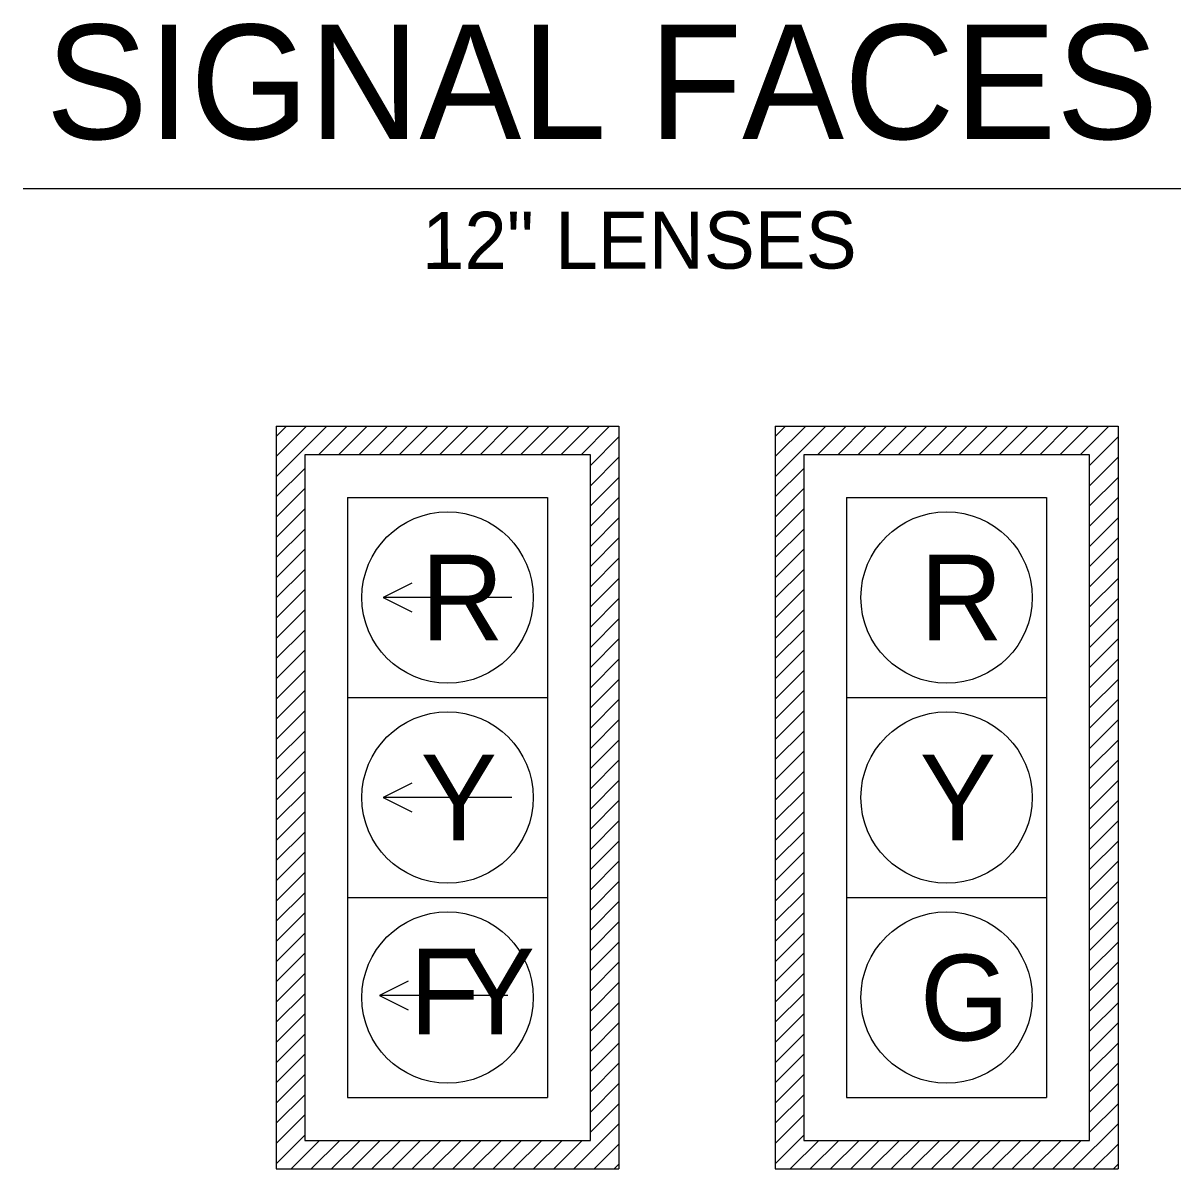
# Model space of a CAD drawing. Extents: x 1845362 to 1846362, y 750211 to 750851.
# Drawn here: x 1845538 to 1845618.5, y 750350.5 to 750430.7 of the extents above; entities that cross this region are included whole.
import ezdxf

# ---------------------------------------------------------------- set-up
doc = ezdxf.new("R2010")
doc.units = 0
doc.layers.add('T_Drafting', color=7, linetype='Continuous')
doc.layers.add('T_Notes', color=7, linetype='Continuous')

msp = doc.modelspace()

# ---------------------------------------------------------------- linework, layer by layer
at = {"layer": 'T_Drafting'}
for p, q in [((1845555.757, 750402.459), (1845579.757, 750402.459)), ((1845555.757, 750402.459), (1845555.757, 750350.459)), ((1845555.757, 750398.912), (1845559.304, 750402.459)), ((1845555.757, 750400.326), (1845557.89, 750402.459)), ((1845555.757, 750401.74), (1845556.475, 750402.459)), ((1845558.718, 750400.459), (1845560.718, 750402.459)), ((1845560.132, 750400.459), (1845562.132, 750402.459)), ((1845561.546, 750400.459), (1845563.546, 750402.459)), ((1845562.961, 750400.459), (1845564.961, 750402.459)), ((1845564.375, 750400.459), (1845566.375, 750402.459)), ((1845565.789, 750400.459), (1845567.789, 750402.459)), ((1845567.203, 750400.459), (1845569.203, 750402.459)), ((1845568.618, 750400.459), (1845570.618, 750402.459)), ((1845570.032, 750400.459), (1845572.032, 750402.459)), ((1845571.446, 750400.459), (1845573.446, 750402.459)), ((1845572.86, 750400.459), (1845574.86, 750402.459)), ((1845574.274, 750400.459), (1845576.274, 750402.459)), ((1845575.689, 750400.459), (1845577.689, 750402.459)), ((1845577.103, 750400.459), (1845579.103, 750402.459)), ((1845579.757, 750402.459), (1845579.757, 750350.459)), ((1845590.695, 750402.459), (1845614.695, 750402.459)), ((1845590.695, 750402.459), (1845590.695, 750350.459)), ((1845590.695, 750398.912), (1845594.242, 750402.459)), ((1845590.695, 750400.326), (1845592.827, 750402.459)), ((1845590.695, 750401.74), (1845591.413, 750402.459)), ((1845593.656, 750400.459), (1845595.656, 750402.459)), ((1845595.07, 750400.459), (1845597.07, 750402.459)), ((1845596.484, 750400.459), (1845598.484, 750402.459)), ((1845597.898, 750400.459), (1845599.898, 750402.459)), ((1845599.313, 750400.459), (1845601.313, 750402.459)), ((1845600.727, 750400.459), (1845602.727, 750402.459)), ((1845602.141, 750400.459), (1845604.141, 750402.459)), ((1845603.555, 750400.459), (1845605.555, 750402.459)), ((1845604.97, 750400.459), (1845606.97, 750402.459)), ((1845606.384, 750400.459), (1845608.384, 750402.459)), ((1845607.798, 750400.459), (1845609.798, 750402.459)), ((1845609.212, 750400.459), (1845611.212, 750402.459)), ((1845610.626, 750400.459), (1845612.626, 750402.459)), ((1845612.041, 750400.459), (1845614.041, 750402.459)), ((1845614.695, 750402.459), (1845614.695, 750350.459)), ((1845577.757, 750399.699), (1845579.757, 750401.699)), ((1845612.695, 750399.699), (1845614.695, 750401.699)), ((1845577.757, 750398.285), (1845579.757, 750400.285)), ((1845612.695, 750398.285), (1845614.695, 750400.285)), ((1845555.757, 750397.498), (1845557.757, 750399.498)), ((1845590.695, 750397.498), (1845592.695, 750399.498)), ((1845577.757, 750396.87), (1845579.757, 750398.87)), ((1845612.695, 750396.87), (1845614.695, 750398.87)), ((1845555.757, 750396.084), (1845557.757, 750398.084)), ((1845590.695, 750396.084), (1845592.695, 750398.084)), ((1845560.757, 750397.459), (1845574.757, 750397.459)), ((1845560.757, 750397.459), (1845560.757, 750383.459)), ((1845574.757, 750397.459), (1845574.757, 750383.459)), ((1845577.757, 750395.456), (1845579.757, 750397.456)), ((1845595.695, 750397.459), (1845609.695, 750397.459)), ((1845595.695, 750397.459), (1845595.695, 750383.459)), ((1845609.695, 750397.459), (1845609.695, 750383.459)), ((1845612.695, 750395.456), (1845614.695, 750397.456)), ((1845555.757, 750394.669), (1845557.757, 750396.669)), ((1845590.695, 750394.669), (1845592.695, 750396.669)), ((1845577.757, 750394.042), (1845579.757, 750396.042)), ((1845612.695, 750394.042), (1845614.695, 750396.042)), ((1845555.757, 750393.255), (1845557.757, 750395.255)), ((1845577.757, 750392.628), (1845579.757, 750394.628)), ((1845590.695, 750393.255), (1845592.695, 750395.255)), ((1845612.695, 750392.628), (1845614.695, 750394.628)), ((1845555.757, 750391.841), (1845557.757, 750393.841)), ((1845590.695, 750391.841), (1845592.695, 750393.841)), ((1845577.757, 750391.214), (1845579.757, 750393.214)), ((1845612.695, 750391.214), (1845614.695, 750393.214)), ((1845555.757, 750390.427), (1845557.757, 750392.427)), ((1845590.695, 750390.427), (1845592.695, 750392.427)), ((1845577.757, 750389.799), (1845579.757, 750391.799)), ((1845612.695, 750389.799), (1845614.695, 750391.799)), ((1845555.757, 750389.013), (1845557.757, 750391.013)), ((1845590.695, 750389.013), (1845592.695, 750391.013)), ((1845572.257, 750390.459), (1845563.257, 750390.459)), ((1845577.757, 750388.385), (1845579.757, 750390.385)), ((1845612.695, 750388.385), (1845614.695, 750390.385)), ((1845555.757, 750387.598), (1845557.757, 750389.598)), ((1845577.757, 750386.971), (1845579.757, 750388.971)), ((1845590.695, 750387.598), (1845592.695, 750389.598)), ((1845612.695, 750386.971), (1845614.695, 750388.971)), ((1845555.757, 750386.184), (1845557.757, 750388.184)), ((1845590.695, 750386.184), (1845592.695, 750388.184)), ((1845577.757, 750385.557), (1845579.757, 750387.557)), ((1845612.695, 750385.557), (1845614.695, 750387.557)), ((1845555.757, 750384.77), (1845557.757, 750386.77)), ((1845590.695, 750384.77), (1845592.695, 750386.77)), ((1845577.757, 750384.142), (1845579.757, 750386.142)), ((1845612.695, 750384.142), (1845614.695, 750386.142)), ((1845555.757, 750383.356), (1845557.757, 750385.356)), ((1845590.695, 750383.356), (1845592.695, 750385.356)), ((1845577.757, 750382.728), (1845579.757, 750384.728)), ((1845612.695, 750382.728), (1845614.695, 750384.728)), ((1845555.757, 750381.941), (1845557.757, 750383.941)), ((1845560.757, 750383.459), (1845574.757, 750383.459)), ((1845560.757, 750383.459), (1845560.757, 750369.459)), ((1845574.757, 750383.459), (1845574.757, 750369.459)), ((1845577.757, 750381.314), (1845579.757, 750383.314)), ((1845590.695, 750381.941), (1845592.695, 750383.941)), ((1845595.695, 750383.459), (1845609.695, 750383.459)), ((1845595.695, 750383.459), (1845595.695, 750369.459)), ((1845609.695, 750383.459), (1845609.695, 750369.459)), ((1845612.695, 750381.314), (1845614.695, 750383.314)), ((1845555.757, 750380.527), (1845557.757, 750382.527)), ((1845590.695, 750380.527), (1845592.695, 750382.527)), ((1845577.757, 750379.9), (1845579.757, 750381.9)), ((1845612.695, 750379.9), (1845614.695, 750381.9)), ((1845555.757, 750379.113), (1845557.757, 750381.113)), ((1845590.695, 750379.113), (1845592.695, 750381.113)), ((1845577.757, 750378.486), (1845579.757, 750380.486)), ((1845612.695, 750378.486), (1845614.695, 750380.486)), ((1845555.757, 750377.699), (1845557.757, 750379.699)), ((1845590.695, 750377.699), (1845592.695, 750379.699)), ((1845577.757, 750377.071), (1845579.757, 750379.071)), ((1845612.695, 750377.071), (1845614.695, 750379.071)), ((1845555.757, 750376.285), (1845557.757, 750378.285)), ((1845577.757, 750375.657), (1845579.757, 750377.657)), ((1845590.695, 750376.285), (1845592.695, 750378.285)), ((1845612.695, 750375.657), (1845614.695, 750377.657)), ((1845555.757, 750374.87), (1845557.757, 750376.87)), ((1845590.695, 750374.87), (1845592.695, 750376.87)), ((1845572.257, 750376.459), (1845563.257, 750376.459)), ((1845577.757, 750374.243), (1845579.757, 750376.243)), ((1845612.695, 750374.243), (1845614.695, 750376.243)), ((1845555.757, 750373.456), (1845557.757, 750375.456)), ((1845590.695, 750373.456), (1845592.695, 750375.456)), ((1845577.757, 750372.829), (1845579.757, 750374.829)), ((1845612.695, 750372.829), (1845614.695, 750374.829)), ((1845555.757, 750372.042), (1845557.757, 750374.042)), ((1845590.695, 750372.042), (1845592.695, 750374.042)), ((1845577.757, 750371.415), (1845579.757, 750373.415)), ((1845612.695, 750371.415), (1845614.695, 750373.415)), ((1845555.757, 750370.628), (1845557.757, 750372.628)), ((1845577.757, 750370), (1845579.757, 750372)), ((1845590.695, 750370.628), (1845592.695, 750372.628)), ((1845612.695, 750370), (1845614.695, 750372)), ((1845555.757, 750369.214), (1845557.757, 750371.214)), ((1845590.695, 750369.214), (1845592.695, 750371.214)), ((1845577.757, 750368.586), (1845579.757, 750370.586)), ((1845612.695, 750368.586), (1845614.695, 750370.586)), ((1845555.757, 750367.799), (1845557.757, 750369.799)), ((1845590.695, 750367.799), (1845592.695, 750369.799)), ((1845560.757, 750369.459), (1845574.757, 750369.459)), ((1845560.757, 750369.459), (1845560.757, 750355.459)), ((1845574.757, 750369.459), (1845574.757, 750355.459)), ((1845577.757, 750367.172), (1845579.757, 750369.172)), ((1845595.695, 750369.459), (1845609.695, 750369.459)), ((1845595.695, 750369.459), (1845595.695, 750355.459)), ((1845609.695, 750369.459), (1845609.695, 750355.459)), ((1845612.695, 750367.172), (1845614.695, 750369.172)), ((1845555.757, 750366.385), (1845557.757, 750368.385)), ((1845590.695, 750366.385), (1845592.695, 750368.385)), ((1845577.757, 750365.758), (1845579.757, 750367.758)), ((1845612.695, 750365.758), (1845614.695, 750367.758)), ((1845555.757, 750364.971), (1845557.757, 750366.971)), ((1845577.757, 750364.343), (1845579.757, 750366.343)), ((1845590.695, 750364.971), (1845592.695, 750366.971)), ((1845612.695, 750364.343), (1845614.695, 750366.343)), ((1845555.757, 750363.557), (1845557.757, 750365.557)), ((1845590.695, 750363.557), (1845592.695, 750365.557)), ((1845577.757, 750362.929), (1845579.757, 750364.929)), ((1845612.695, 750362.929), (1845614.695, 750364.929)), ((1845555.757, 750362.142), (1845557.757, 750364.142)), ((1845590.695, 750362.142), (1845592.695, 750364.142)), ((1845577.757, 750361.515), (1845579.757, 750363.515)), ((1845612.695, 750361.515), (1845614.695, 750363.515)), ((1845555.757, 750360.728), (1845557.757, 750362.728)), ((1845571.987, 750362.602), (1845562.987, 750362.602)), ((1845590.695, 750360.728), (1845592.695, 750362.728)), ((1845577.757, 750360.101), (1845579.757, 750362.101)), ((1845612.695, 750360.101), (1845614.695, 750362.101)), ((1845555.757, 750359.314), (1845557.757, 750361.314)), ((1845590.695, 750359.314), (1845592.695, 750361.314)), ((1845555.757, 750357.9), (1845557.757, 750359.9)), ((1845577.757, 750358.687), (1845579.757, 750360.687)), ((1845590.695, 750357.9), (1845592.695, 750359.9)), ((1845612.695, 750358.687), (1845614.695, 750360.687)), ((1845577.757, 750357.272), (1845579.757, 750359.272)), ((1845612.695, 750357.272), (1845614.695, 750359.272)), ((1845555.757, 750356.486), (1845557.757, 750358.486)), ((1845590.695, 750356.486), (1845592.695, 750358.486)), ((1845577.757, 750355.858), (1845579.757, 750357.858)), ((1845612.695, 750355.858), (1845614.695, 750357.858)), ((1845555.757, 750355.071), (1845557.757, 750357.071)), ((1845590.695, 750355.071), (1845592.695, 750357.071)), ((1845577.757, 750354.444), (1845579.757, 750356.444)), ((1845612.695, 750354.444), (1845614.695, 750356.444)), ((1845555.757, 750353.657), (1845557.757, 750355.657)), ((1845560.757, 750355.459), (1845574.757, 750355.459)), ((1845590.695, 750353.657), (1845592.695, 750355.657)), ((1845595.695, 750355.459), (1845609.695, 750355.459)), ((1845577.757, 750353.03), (1845579.757, 750355.03)), ((1845612.695, 750353.03), (1845614.695, 750355.03)), ((1845555.757, 750352.243), (1845557.757, 750354.243)), ((1845576.6, 750350.459), (1845579.757, 750353.616)), ((1845590.695, 750352.243), (1845592.695, 750354.243)), ((1845611.538, 750350.459), (1845614.695, 750353.616)), ((1845555.757, 750350.829), (1845557.757, 750352.829)), ((1845590.695, 750350.829), (1845592.695, 750352.829)), ((1845556.801, 750350.459), (1845558.801, 750352.459)), ((1845558.215, 750350.459), (1845560.215, 750352.459)), ((1845559.63, 750350.459), (1845561.63, 750352.459)), ((1845561.044, 750350.459), (1845563.044, 750352.459)), ((1845562.458, 750350.459), (1845564.458, 750352.459)), ((1845563.872, 750350.459), (1845565.872, 750352.459)), ((1845565.287, 750350.459), (1845567.287, 750352.459)), ((1845566.701, 750350.459), (1845568.701, 750352.459)), ((1845568.115, 750350.459), (1845570.115, 750352.459)), ((1845569.529, 750350.459), (1845571.529, 750352.459)), ((1845570.943, 750350.459), (1845572.943, 750352.459)), ((1845572.358, 750350.459), (1845574.358, 750352.459)), ((1845573.772, 750350.459), (1845575.772, 750352.459)), ((1845575.186, 750350.459), (1845577.186, 750352.459)), ((1845578.014, 750350.459), (1845579.757, 750352.201)), ((1845591.739, 750350.459), (1845593.739, 750352.459)), ((1845593.153, 750350.459), (1845595.153, 750352.459)), ((1845594.568, 750350.459), (1845596.568, 750352.459)), ((1845595.982, 750350.459), (1845597.982, 750352.459)), ((1845597.396, 750350.459), (1845599.396, 750352.459)), ((1845598.81, 750350.459), (1845600.81, 750352.459)), ((1845600.224, 750350.459), (1845602.224, 750352.459)), ((1845601.639, 750350.459), (1845603.639, 750352.459)), ((1845603.053, 750350.459), (1845605.053, 750352.459)), ((1845604.467, 750350.459), (1845606.467, 750352.459)), ((1845605.881, 750350.459), (1845607.881, 750352.459)), ((1845607.295, 750350.459), (1845609.295, 750352.459)), ((1845608.71, 750350.459), (1845610.71, 750352.459)), ((1845610.124, 750350.459), (1845612.124, 750352.459)), ((1845612.952, 750350.459), (1845614.695, 750352.201)), ((1845555.757, 750350.459), (1845579.757, 750350.459)), ((1845579.429, 750350.459), (1845579.757, 750350.787)), ((1845590.695, 750350.459), (1845614.695, 750350.459)), ((1845614.367, 750350.459), (1845614.695, 750350.787))]:
    msp.add_line(p, q, dxfattribs=at)
for points in [[(1845577.757, 750352.459), (1845577.757, 750400.459), (1845557.757, 750400.459), (1845557.757, 750352.459)], [(1845612.695, 750352.459), (1845612.695, 750400.459), (1845592.695, 750400.459), (1845592.695, 750352.459)]]:
    msp.add_lwpolyline(points, close=True, dxfattribs=at)
for points in [[(1845565.257, 750391.459), (1845563.257, 750390.459), (1845565.257, 750389.459)], [(1845565.257, 750377.459), (1845563.257, 750376.459), (1845565.257, 750375.459)], [(1845564.987, 750363.602), (1845562.987, 750362.602), (1845564.987, 750361.602)]]:
    msp.add_lwpolyline(points, dxfattribs=at)
for centre in [(1845567.757, 750390.459), (1845602.695, 750390.459), (1845567.757, 750376.459), (1845602.695, 750376.459), (1845567.757, 750362.459), (1845602.695, 750362.459)]:
    msp.add_circle(centre, 6, dxfattribs=at)
at = {"layer": 'T_Notes'}
msp.add_line((1845538.033, 750419.086), (1845636.218, 750419.086), dxfattribs=at)

# ---------------------------------------------------------------- texts
at = {"layer": 'T_Drafting'}
msp.add_text('12" LENSES', height=4, rotation=0.07203, dxfattribs=at).set_placement((1845565.959, 750413.452))
for s, p in [('R', (1845565.892, 750387.46)), ('R', (1845600.83, 750387.46)), ('Y', (1845565.868, 750373.46)), ('Y', (1845600.806, 750373.46)), ('F', (1845565.107, 750359.88)), ('Y', (1845568.531, 750359.88)), ('G', (1845600.829, 750359.46))]:
    msp.add_text(s, height=5.998, dxfattribs=at).set_placement(p)
at = {"layer": 'T_Notes'}
msp.add_text('SIGNAL FACES', height=8, dxfattribs=at).set_placement((1845539.631, 750422.555))

doc.saveas('drawing.dxf')
